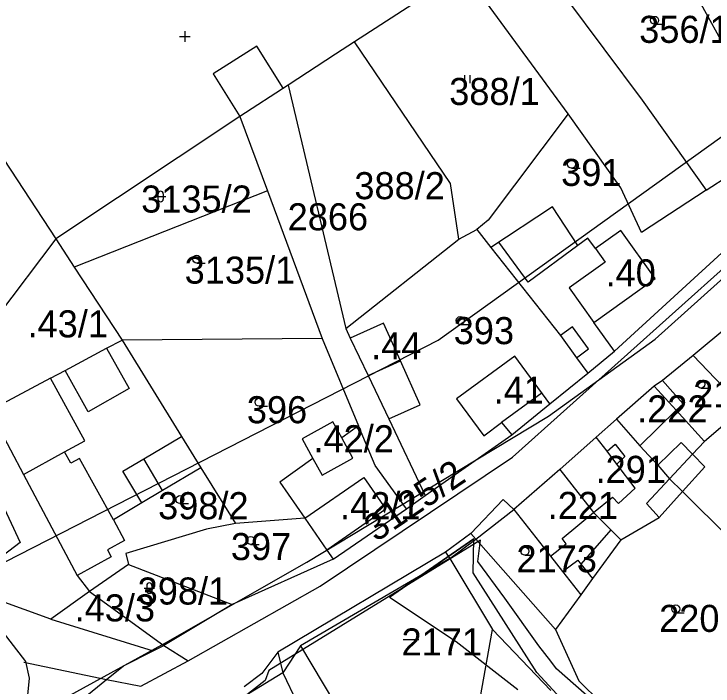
# Model space of a CAD drawing. Extents: x -564810 to -550519, y -1045831 to -1034011.
# Drawn here: x -553398.7 to -553266.8, y -1036818.2 to -1036691.5 of the extents above; entities that cross this region are included whole.
import ezdxf

# ---------------------------------------------------------------- set-up
doc = ezdxf.new("R2010")
doc.units = 0
for name, color, linetype in [('KN stav', 7, 'Continuous'), ('Obvod KPU', 7, 'Continuous'), ('Parcelní čísla', 7, 'Continuous'), ('Polní cesty stavající', 7, 'Continuous'), ('STG', 7, 'Continuous'), ('Vrstva 22', 7, 'Continuous'), ('Vrstva 33', 7, 'Continuous'), ('Vrstva 4', 7, 'Continuous'), ('zamokř ploch', 7, 'Continuous')]:
    doc.layers.add(name, color=color, linetype=linetype)

msp = doc.modelspace()

# ---------------------------------------------------------------- linework, layer by layer
at = {"layer": 'KN stav'}
for p, q in [((-553303.5, -1036676.52), (-553280.2, -1036707.72)), ((-553313.89, -1036683.4), (-553334.42, -1036696.74)), ((-553294.13, -1036710.29), (-553313.89, -1036683.4)), ((-553269.1, -1036689.57), (-553264.42, -1036698.14)), ((-553418.09, -1036692.22), (-553390.79, -1036733.87)), ((-553334.42, -1036696.74), (-553338.02, -1036699.08)), ((-553316.35, -1036723.42), (-553334.42, -1036696.74)), ((-553338.02, -1036699.08), (-553346.96, -1036704.89)), ((-553346.96, -1036704.89), (-553356.04, -1036710.79)), ((-553346.96, -1036704.89), (-553336.1, -1036750.77)), ((-553280.2, -1036707.72), (-553268.1, -1036724.68)), ((-553356.04, -1036710.79), (-553390.79, -1036733.87)), ((-553356.04, -1036710.79), (-553350.84, -1036724.85)), ((-553294.13, -1036710.29), (-553309.2, -1036730.37)), ((-553284.18, -1036724.24), (-553294.13, -1036710.29)), ((-553268.1, -1036724.68), (-553256.44, -1036717.04)), ((-553314.74, -1036733.92), (-553316.35, -1036723.42)), ((-553285.39, -1036755.08), (-553251.88, -1036724.28)), ((-553280.32, -1036732.69), (-553284.18, -1036724.24)), ((-553350.84, -1036724.85), (-553387.29, -1036739.2)), ((-553350.84, -1036724.85), (-553340.54, -1036752.69)), ((-553268.1, -1036724.68), (-553280.32, -1036732.69)), ((-553304.61, -1036775.06), (-553250.68, -1036726.67)), ((-553297.09, -1036727.85), (-553308.71, -1036735.48)), ((-553292.31, -1036735.14), (-553297.09, -1036727.85)), ((-553309.2, -1036730.37), (-553311.36, -1036732.11)), ((-553314.74, -1036733.92), (-553311.36, -1036732.11)), ((-553311.36, -1036732.11), (-553308.71, -1036735.48)), ((-553284.23, -1036732.32), (-553288.97, -1036735.71)), ((-553277.74, -1036741.38), (-553284.23, -1036732.32)), ((-553390.79, -1036733.87), (-553414.68, -1036765.53)), ((-553390.79, -1036733.87), (-553387.29, -1036739.2)), ((-553336.1, -1036750.77), (-553314.74, -1036733.92)), ((-553290.4, -1036733.73), (-553292.31, -1036735.14)), ((-553288.97, -1036735.71), (-553290.4, -1036733.73)), ((-553308.71, -1036735.48), (-553295.61, -1036752.12)), ((-553387.29, -1036739.2), (-553378.28, -1036752.95)), ((-553289.28, -1036749.64), (-553277.74, -1036741.38)), ((-553328.95, -1036749.79), (-553335.23, -1036752.6)), ((-553325.77, -1036756.9), (-553328.95, -1036749.79)), ((-553285.39, -1036755.08), (-553289.28, -1036749.64)), ((-553263.85, -1036750.26), (-553270.55, -1036755.88)), ((-553336.1, -1036750.77), (-553335.23, -1036752.6)), ((-553340.54, -1036752.69), (-553378.28, -1036752.95)), ((-553378.28, -1036752.95), (-553367.05, -1036771.12)), ((-553340.54, -1036752.69), (-553333.67, -1036769.12)), ((-553335.23, -1036752.6), (-553331.88, -1036759.64)), ((-553295.61, -1036752.12), (-553292.57, -1036756.28)), ((-553304.17, -1036755.98), (-553315.17, -1036764.06)), ((-553297.57, -1036764.97), (-553304.17, -1036755.98)), ((-553290.45, -1036759.18), (-553285.39, -1036755.08)), ((-553270.55, -1036755.88), (-553276.33, -1036760.55)), ((-553270.55, -1036755.88), (-553261.11, -1036765.8)), ((-553322.07, -1036765.16), (-553325.77, -1036756.9)), ((-553292.57, -1036756.28), (-553290.45, -1036759.18)), ((-553331.88, -1036759.64), (-553327.99, -1036767.81)), ((-553297.57, -1036764.97), (-553290.45, -1036759.18)), ((-553276.33, -1036760.55), (-553277.9, -1036761.67)), ((-553276.33, -1036760.55), (-553272.43, -1036764.96)), ((-553277.9, -1036761.67), (-553285.04, -1036767.87)), ((-553327.99, -1036767.81), (-553322.07, -1036765.16)), ((-553315.17, -1036764.06), (-553310.07, -1036771)), ((-553304.77, -1036770.82), (-553297.57, -1036764.97)), ((-553272.43, -1036764.96), (-553273.77, -1036766.19)), ((-553273.77, -1036766.19), (-553268.43, -1036772.06)), ((-553261.11, -1036765.8), (-553268.43, -1036772.06)), ((-553327.99, -1036767.81), (-553321.1, -1036782.28)), ((-553285.04, -1036767.87), (-553288.83, -1036771.24)), ((-553285.04, -1036767.87), (-553280.63, -1036772.89)), ((-553338.51, -1036768.39), (-553344.32, -1036771.58)), ((-553336.85, -1036771.4), (-553338.51, -1036768.39)), ((-553333.67, -1036769.12), (-553336.85, -1036771.4)), ((-553330.55, -1036776.58), (-553333.67, -1036769.12)), ((-553310.07, -1036771), (-553306.68, -1036768.5)), ((-553306.68, -1036768.5), (-553304.77, -1036770.82)), ((-553367.05, -1036771.12), (-553363.4, -1036777.03)), ((-553344.32, -1036771.58), (-553342.29, -1036775.28)), ((-553334.74, -1036775.25), (-553336.85, -1036771.4)), ((-553321.1, -1036782.28), (-553304.77, -1036770.82)), ((-553288.83, -1036771.24), (-553295.7, -1036777.37)), ((-553280.63, -1036772.89), (-553277.23, -1036776.57)), ((-553268.43, -1036772.06), (-553270.66, -1036774.46)), ((-553270.66, -1036774.46), (-553268.36, -1036776.88)), ((-553342.29, -1036775.28), (-553348.52, -1036779.73)), ((-553342.29, -1036775.28), (-553340.55, -1036778.44)), ((-553340.88, -1036799.38), (-553304.61, -1036775.06)), ((-553340.55, -1036778.44), (-553334.74, -1036775.25)), ((-553363.4, -1036777.03), (-553370.63, -1036781.34)), ((-553363.4, -1036777.03), (-553356.9, -1036787.55)), ((-553324.64, -1036784.77), (-553330.55, -1036776.58)), ((-553277.23, -1036776.57), (-553275, -1036779.15)), ((-553268.36, -1036776.88), (-553272.56, -1036781.53)), ((-553295.7, -1036777.37), (-553304.4, -1036784.89)), ((-553295.7, -1036777.37), (-553289.38, -1036785.48)), ((-553348.52, -1036779.73), (-553343.8, -1036786.56)), ((-553275, -1036779.15), (-553272.56, -1036781.53)), ((-553402.2, -1036781.1), (-553397.52, -1036791.1)), ((-553370.63, -1036781.34), (-553374.55, -1036783.67)), ((-553324.64, -1036784.77), (-553321.1, -1036782.28)), ((-553276.97, -1036786.43), (-553272.56, -1036781.53)), ((-553272.56, -1036781.53), (-553249.99, -1036803.99)), ((-553374.55, -1036783.67), (-553379.91, -1036786.86)), ((-553306.38, -1036783.01), (-553312.5, -1036789.42)), ((-553304.4, -1036784.89), (-553306.38, -1036783.01)), ((-553338.46, -1036794.28), (-553324.64, -1036784.77)), ((-553304.4, -1036784.89), (-553297.46, -1036793.73)), ((-553289.38, -1036785.48), (-553286.1, -1036788.74)), ((-553379.91, -1036786.86), (-553377.79, -1036790.73)), ((-553356.9, -1036787.55), (-553362.33, -1036788.59)), ((-553343.8, -1036786.56), (-553356.9, -1036787.55)), ((-553343.8, -1036786.56), (-553339.67, -1036792.54)), ((-553284.23, -1036790.6), (-553276.97, -1036786.43)), ((-553362.33, -1036788.59), (-553377.58, -1036793.17)), ((-553286.1, -1036788.74), (-553284.23, -1036790.6)), ((-553312.5, -1036789.42), (-553317.26, -1036792.96)), ((-553312.5, -1036789.42), (-553311.55, -1036790.5)), ((-553397.52, -1036791.1), (-553407.66, -1036798.87)), ((-553377.79, -1036790.73), (-553381.04, -1036792.52)), ((-553311.55, -1036790.5), (-553296.54, -1036807.54)), ((-553284.23, -1036790.6), (-553289.52, -1036797.89)), ((-553381.04, -1036792.52), (-553380.34, -1036793.8)), ((-553339.67, -1036792.54), (-553338.46, -1036794.28)), ((-553380.34, -1036793.8), (-553386.76, -1036797.33)), ((-553377.58, -1036793.17), (-553377.03, -1036795.28)), ((-553317.26, -1036792.96), (-553348.87, -1036811.79)), ((-553316.44, -1036794.15), (-553344.62, -1036810.59)), ((-553317.26, -1036792.96), (-553316.44, -1036794.15)), ((-553316.44, -1036794.15), (-553308.39, -1036807.51)), ((-553297.46, -1036793.73), (-553295.21, -1036796.59)), ((-553377.03, -1036795.28), (-553384.39, -1036800.33)), ((-553377.03, -1036795.28), (-553357.5, -1036802.78)), ((-553338.46, -1036794.28), (-553357.5, -1036802.78)), ((-553295.21, -1036796.59), (-553291.77, -1036800.97)), ((-553386.76, -1036797.33), (-553384.39, -1036800.33)), ((-553289.52, -1036797.89), (-553291.77, -1036800.97)), ((-553365.82, -1036813.44), (-553340.88, -1036799.38)), ((-553391.72, -1036805.55), (-553406.3, -1036800.33)), ((-553384.39, -1036800.33), (-553391.72, -1036805.55)), ((-553384.39, -1036800.33), (-553370.37, -1036810.51)), ((-553291.77, -1036800.97), (-553296.54, -1036807.54)), ((-553357.5, -1036802.78), (-553370.37, -1036810.51)), ((-553403.71, -1036804.22), (-553396.47, -1036813.58)), ((-553391.72, -1036805.55), (-553372.38, -1036811.54)), ((-553310.76, -1036820.54), (-553308.39, -1036807.51)), ((-553308.39, -1036807.51), (-553297.38, -1036819)), ((-553296.54, -1036807.54), (-553292.1, -1036817.2)), ((-553372.38, -1036811.54), (-553370.37, -1036810.51)), ((-553370.37, -1036810.51), (-553365.82, -1036813.44)), ((-553344.62, -1036810.59), (-553336.21, -1036824.69)), ((-553348.87, -1036811.79), (-553351.92, -1036815.83)), ((-553348.87, -1036811.79), (-553347.94, -1036815.7)), ((-553396.47, -1036813.58), (-553395.79, -1036816.73)), ((-553351.92, -1036815.83), (-553355.26, -1036818.32)), ((-553347.94, -1036815.7), (-553344.15, -1036823.53)), ((-553398.1, -1036830.48), (-553381.22, -1036816.98)), ((-553395.79, -1036816.73), (-553396.18, -1036820.54)), ((-553381.22, -1036816.98), (-553374.73, -1036818.18)), ((-553292.1, -1036817.2), (-553273.82, -1036835.26))]:
    msp.add_line(p, q, dxfattribs=at)
at = {"layer": 'Obvod KPU'}
for p, q in [((-553310.65, -1036790.68), (-553350.57, -1036815.23)), ((-553311.17, -1036794.7), (-553310.65, -1036790.68)), ((-553306.11, -1036801.6), (-553311.17, -1036794.7)), ((-553299.66, -1036810.61), (-553306.11, -1036801.6)), ((-553297.43, -1036813.48), (-553299.66, -1036810.61)), ((-553296.32, -1036814.94), (-553297.43, -1036813.48)), ((-553350.57, -1036815.23), (-553351.3, -1036817.14)), ((-553272.29, -1036836), (-553296.32, -1036814.94)), ((-553351.3, -1036817.14), (-553355.33, -1036820.26))]:
    msp.add_line(p, q, dxfattribs=at)
at = {"layer": 'Polní cesty stavající'}
for p, q in [((-553327.84, -1036801.43), (-553311.9, -1036790.4)), ((-553311.9, -1036790.4), (-553327.84, -1036801.43)), ((-553312.05, -1036796.81), (-553311.9, -1036790.4)), ((-553300.04, -1036815.62), (-553312.05, -1036796.81)), ((-553327.84, -1036801.43), (-553315.27, -1036809.8)), ((-553315.27, -1036809.8), (-553303.65, -1036818.85)), ((-553283.82, -1036833.12), (-553300.04, -1036815.62))]:
    msp.add_line(p, q, dxfattribs=at)
at = {"layer": 'STG'}
msp.add_lwpolyline([(-553913.89, -1037214.19), (-553796.31, -1037140.69), (-553706.3, -1037067.18), (-553629.14, -1036991.84), (-553566.68, -1036914.66), (-553476.66, -1036833.81), (-553318.67, -1036752.96), (-553234.16, -1036692.32), (-553142.31, -1036650.05), (-553048.61, -1036626.16), (-552953.09, -1036624.32), (-552903.48, -1036624.32), (-552861.23, -1036602.27), (-552798.77, -1036576.55), (-552738.15, -1036530.61), (-552646.29, -1036431.38), (-552581.99, -1036368.9), (-552545.25, -1036306.42), (-552506.67, -1036223.73), (-552482.79, -1036161.25), (-552440.54, -1036117.15)], dxfattribs=at)
at = {"layer": 'Vrstva 33'}
msp.add_lwpolyline([(-553437.86, -1037027.66), (-553431.51, -1036952.06), (-553425.86, -1036904.01), (-553418.79, -1036878.58), (-553403.96, -1036844.66), (-553391.96, -1036822.05), (-553370.06, -1036810.04), (-553343.4, -1036794.85), (-553314.8, -1036777.54), (-553297.85, -1036767.29), (-553277.72, -1036752.81), (-553253.71, -1036731.26), (-553251.95, -1036725.61), (-553243.83, -1036717.84), (-553220.52, -1036713.6), (-553180.16, -1036709.5), (-553163.92, -1036709.85), (-553122.95, -1036708.79)], dxfattribs=at)
at = {"layer": 'Vrstva 4'}
for p, q in [((-553352.86, -1036697.57), (-553361.1, -1036702.78)), ((-553347.86, -1036705.47), (-553352.86, -1036697.57)), ((-553361.1, -1036702.78), (-553356.04, -1036710.78)), ((-553301.65, -1036742.05), (-553307.21, -1036734.49)), ((-553292.31, -1036735.14), (-553301.65, -1036742.05)), ((-553288.98, -1036735.71), (-553287.15, -1036738.26)), ((-553287.15, -1036738.26), (-553293.94, -1036743.12)), ((-553293.94, -1036743.12), (-553289.28, -1036749.64)), ((-553293.35, -1036750.46), (-553295.61, -1036752.12)), ((-553290.31, -1036754.62), (-553293.35, -1036750.46)), ((-553381.2, -1036754.5), (-553378.28, -1036752.95)), ((-553389.03, -1036758.68), (-553381.2, -1036754.5)), ((-553381.2, -1036754.5), (-553376.91, -1036762.11)), ((-553292.57, -1036756.28), (-553290.31, -1036754.62)), ((-553331.88, -1036759.63), (-553325.77, -1036756.9)), ((-553391.75, -1036760.13), (-553389.03, -1036758.68)), ((-553384.64, -1036766.47), (-553389.03, -1036758.68)), ((-553391.75, -1036760.13), (-553403.24, -1036766.27)), ((-553385.27, -1036771.93), (-553391.75, -1036760.13)), ((-553376.91, -1036762.11), (-553384.64, -1036766.47)), ((-553273.77, -1036766.19), (-553277.9, -1036761.67)), ((-553299.07, -1036762.92), (-553306.68, -1036768.5)), ((-553403.24, -1036766.27), (-553396.86, -1036778.29)), ((-553280.63, -1036772.89), (-553273.77, -1036766.19)), ((-553374.18, -1036775.36), (-553367.05, -1036771.12)), ((-553286.8, -1036773.89), (-553288.83, -1036771.24)), ((-553389.11, -1036774.04), (-553385.27, -1036771.93)), ((-553286.8, -1036773.89), (-553285.29, -1036772.57)), ((-553285.29, -1036772.57), (-553283.44, -1036774.89)), ((-553272.82, -1036772.26), (-553277.23, -1036776.57)), ((-553270.66, -1036774.46), (-553272.82, -1036772.26)), ((-553396.86, -1036778.29), (-553389.11, -1036774.04)), ((-553387.94, -1036776.17), (-553389.11, -1036774.04)), ((-553284.94, -1036776.33), (-553286.8, -1036773.89)), ((-553270.66, -1036774.46), (-553275, -1036779.15)), ((-553386.28, -1036775.26), (-553387.94, -1036776.17)), ((-553379.91, -1036786.86), (-553386.28, -1036775.26)), ((-553378.1, -1036777.7), (-553374.18, -1036775.36)), ((-553370.63, -1036781.33), (-553374.18, -1036775.36)), ((-553283.44, -1036774.89), (-553284.94, -1036776.33)), ((-553281.48, -1036780.86), (-553284.94, -1036776.33)), ((-553396.86, -1036778.29), (-553386.77, -1036797.32)), ((-553374.55, -1036783.67), (-553378.1, -1036777.7)), ((-553343.8, -1036786.56), (-553332.66, -1036778.86)), ((-553332.66, -1036778.86), (-553328.53, -1036784.84)), ((-553275, -1036779.15), (-553279.35, -1036783.76)), ((-553284.62, -1036783.75), (-553281.48, -1036780.86)), ((-553289.38, -1036785.48), (-553285.76, -1036782.56)), ((-553285.76, -1036782.56), (-553284.62, -1036783.75)), ((-553328.53, -1036784.84), (-553339.67, -1036792.54)), ((-553311.55, -1036790.5), (-553304.4, -1036784.89)), ((-553279.35, -1036783.76), (-553276.97, -1036786.42)), ((-553295.29, -1036790.35), (-553289.38, -1036785.48)), ((-553286.11, -1036788.73), (-553291.72, -1036795.19)), ((-553316.44, -1036794.15), (-553311.55, -1036790.5)), ((-553297.46, -1036793.72), (-553294.52, -1036791.38)), ((-553294.52, -1036791.38), (-553295.29, -1036790.35)), ((-553295.21, -1036796.58), (-553292.31, -1036794.47)), ((-553292.31, -1036794.47), (-553291.72, -1036795.19)), ((-553291.72, -1036795.19), (-553289.53, -1036797.88)), ((-553344.62, -1036810.59), (-553347.94, -1036815.7)), ((-553378, -1036814.4), (-553372.38, -1036811.53)), ((-553396.8, -1036813.68), (-553381.22, -1036816.97)), ((-553374.73, -1036818.18), (-553365.82, -1036813.44)), ((-553381.22, -1036816.97), (-553378, -1036814.4)), ((-553347.94, -1036815.7), (-553354.44, -1036819.66))]:
    msp.add_line(p, q, dxfattribs=at)
at = {"layer": 'zamokř ploch'}
for p, q in [((-553277.84, -1036693.43), (-553276.24, -1036693.43)), ((-553366.42, -1036694.71), (-553366.42, -1036696.71)), ((-553367.42, -1036695.71), (-553365.42, -1036695.71)), ((-553313.71, -1036703.03), (-553313.71, -1036704.53)), ((-553312.71, -1036703.03), (-553312.71, -1036704.53)), ((-553293.49, -1036720.57), (-553291.89, -1036720.57)), ((-553371.5, -1036725.38), (-553371.5, -1036726.38)), ((-553370.5, -1036725.38), (-553370.5, -1036726.38)), ((-553372, -1036725.88), (-553370, -1036725.88)), ((-553364.19, -1036738.46), (-553362.59, -1036738.46)), ((-553314.49, -1036750.02), (-553312.9, -1036750.02)), ((-553269.1, -1036762.02), (-553267.5, -1036762.02)), ((-553352.44, -1036765.42), (-553350.84, -1036765.42)), ((-553367.35, -1036783.77), (-553365.75, -1036783.77)), ((-553354.02, -1036791.47), (-553352.42, -1036791.47)), ((-553302.3, -1036793.51), (-553300.7, -1036793.51)), ((-553373.63, -1036799.23), (-553373.63, -1036800.23)), ((-553372.63, -1036799.23), (-553372.63, -1036800.23)), ((-553374.13, -1036799.73), (-553372.13, -1036799.73)), ((-553273.84, -1036804.39), (-553272.24, -1036804.39)), ((-553325.28, -1036809.44), (-553322.28, -1036809.44))]:
    msp.add_line(p, q, dxfattribs=at)
for centre in [(-553277.84, -1036692.68), (-553293.49, -1036719.82), (-553364.19, -1036737.71), (-553314.5, -1036749.27), (-553269.1, -1036761.27), (-553352.44, -1036764.67), (-553367.35, -1036783.02), (-553354.02, -1036790.72), (-553302.3, -1036792.76), (-553273.84, -1036803.64)]:
    msp.add_circle(centre, 0.75, dxfattribs=at)
for centre, start, end in [((-553371, -1036725.38), 0, 180), ((-553371, -1036726.38), 180, 0), ((-553373.13, -1036799.23), 0, 180), ((-553373.13, -1036800.23), 180, 0)]:
    msp.add_arc(centre, 0.5, start, end, dxfattribs=at)

# ---------------------------------------------------------------- texts
at = {"layer": 'Parcelní čísla'}
for s, p in [('356/1', (-553280.74, -1036696.93)), ('388/1', (-553316.57, -1036708.64)), ('391', (-553295.46, -1036723.9)), ('388/2', (-553334.46, -1036726.4)), ('3135/2', (-553374.67, -1036728.92)), ('2866', (-553347.04, -1036732.27)), ('3135/1', (-553366.47, -1036742.32)), ('393', (-553315.72, -1036753.73)), ('2174', (-553270.56, -1036765.62)), ('396', (-553354.74, -1036768.64)), ('398/2', (-553371.48, -1036786.73)), ('397', (-553357.75, -1036794.44)), ('2173', (-553303.89, -1036796.74)), ('398/1', (-553375.33, -1036802.82)), ('2201/2', (-553276.98, -1036807.98)), ('2171', (-553325.56, -1036812.42))]:
    msp.add_text(s, height=5.1, dxfattribs=at).set_placement(p)
msp.add_text('3125/2', height=5.1, rotation=34.1764, dxfattribs=at).set_placement((-553330.35, -1036791.15))
at = {"layer": 'Vrstva 22'}
for s, p in [('.40', (-553287.09, -1036742.84)), ('.43/1', (-553396.1, -1036752.45)), ('.44', (-553331.3, -1036756.58)), ('.41', (-553308.19, -1036764.95)), ('.222', (-553281.13, -1036768.48)), ('.42/2', (-553342.17, -1036774.11)), ('.291', (-553288.97, -1036779.88)), ('.42/1', (-553337.16, -1036786.73)), ('.221', (-553297.99, -1036786.68)), ('.43/3', (-553387.22, -1036806))]:
    msp.add_text(s, height=5.1, dxfattribs=at).set_placement(p)

doc.saveas('drawing.dxf')
